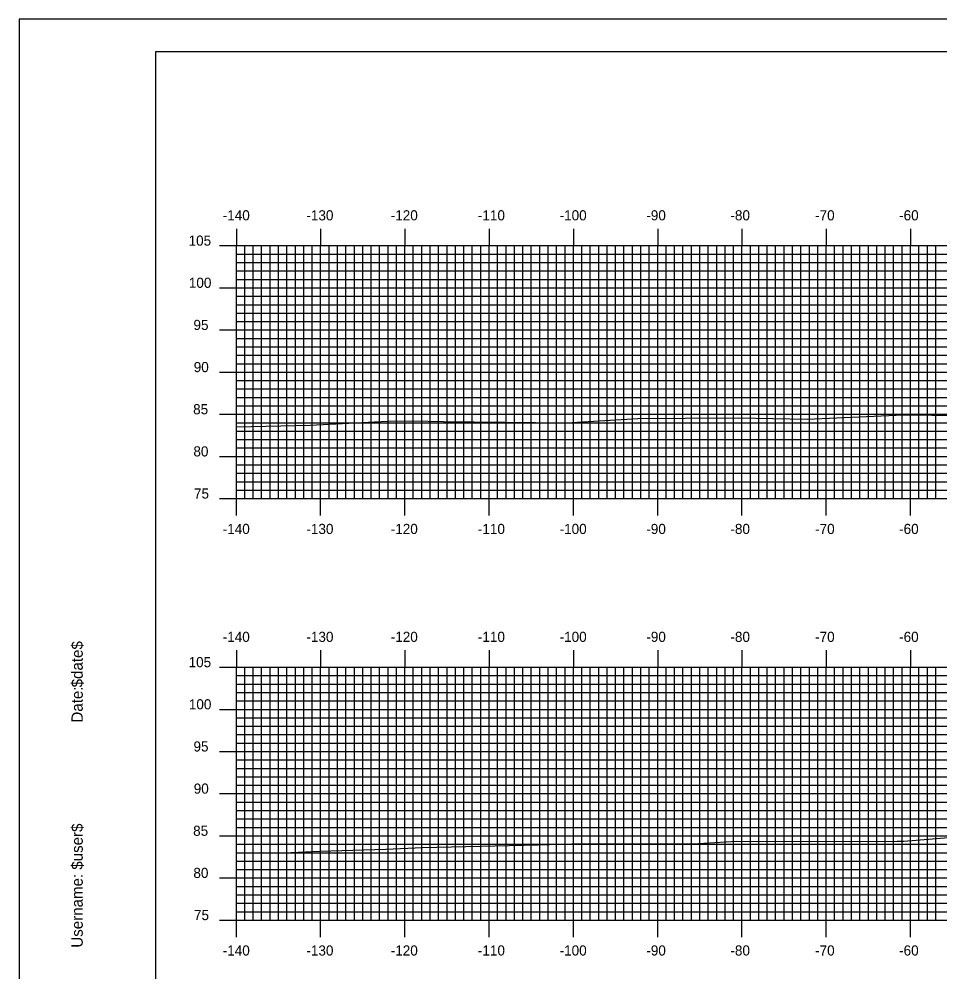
# Model space of a CAD drawing. Extents: x 2059 to 2403, y -1658 to -1438.
# Drawn here: x 2059.4 to 2168.7, y -1550.7 to -1437.7 of the extents above; entities that cross this region are included whole.
import ezdxf

# ---------------------------------------------------------------- set-up
doc = ezdxf.new("R2010")
doc.units = 0
for name, color, linetype in [('BORDER', 7, 'Continuous'), ('H_V ANNOTATION', 7, 'Continuous'), ('MAJOR', 7, 'Continuous'), ('MINOR', 7, 'Continuous'), ('PLOT BOUNDARY', 7, 'Continuous'), ('S_Roadway_Centerline', 7, 'Continuous')]:
    doc.layers.add(name, color=color, linetype=linetype)

msp = doc.modelspace()

# ---------------------------------------------------------------- linework, layer by layer
at = {"layer": 'BORDER'}
msp.add_lwpolyline([(2075.59, -1651.6), (2395.59, -1651.6), (2395.59, -1441.6), (2075.59, -1441.6)], close=True, dxfattribs=at)
at = {"layer": 'MAJOR'}
for p, q in [((2085.19, -1462.6), (2085.19, -1464.6)), ((2095.19, -1462.6), (2095.19, -1464.6)), ((2105.19, -1462.6), (2105.19, -1464.6)), ((2115.19, -1462.6), (2115.19, -1464.6)), ((2125.19, -1462.6), (2125.19, -1464.6)), ((2135.19, -1462.6), (2135.19, -1464.6)), ((2145.19, -1462.6), (2145.19, -1464.6)), ((2155.19, -1462.6), (2155.19, -1464.6)), ((2165.19, -1462.6), (2165.19, -1464.6)), ((2083.18, -1464.6), (2085.19, -1464.6)), ((2085.19, -1464.6), (2365.19, -1464.6)), ((2085.19, -1494.6), (2085.19, -1464.6)), ((2085.19, -1494.6), (2085.19, -1464.6)), ((2085.19, -1464.6), (2365.19, -1464.6)), ((2095.19, -1494.6), (2095.19, -1464.6)), ((2105.19, -1494.6), (2105.19, -1464.6)), ((2115.19, -1494.6), (2115.19, -1464.6)), ((2125.19, -1494.6), (2125.19, -1464.6)), ((2135.19, -1494.6), (2135.19, -1464.6)), ((2145.19, -1494.6), (2145.19, -1464.6)), ((2155.19, -1494.6), (2155.19, -1464.6)), ((2165.19, -1494.6), (2165.19, -1464.6)), ((2083.18, -1469.6), (2085.19, -1469.6)), ((2085.19, -1469.6), (2365.19, -1469.6)), ((2083.18, -1474.6), (2085.19, -1474.6)), ((2085.19, -1474.6), (2365.19, -1474.6)), ((2083.18, -1479.6), (2085.19, -1479.6)), ((2085.19, -1479.6), (2365.19, -1479.6)), ((2083.18, -1484.6), (2085.19, -1484.6)), ((2085.19, -1484.6), (2365.19, -1484.6)), ((2083.18, -1489.6), (2085.19, -1489.6)), ((2085.19, -1489.6), (2365.19, -1489.6)), ((2083.18, -1494.6), (2085.19, -1494.6)), ((2085.19, -1494.6), (2365.19, -1494.6)), ((2085.19, -1494.6), (2365.19, -1494.6)), ((2085.19, -1496.61), (2085.19, -1494.6)), ((2095.19, -1496.61), (2095.19, -1494.6)), ((2105.19, -1496.61), (2105.19, -1494.6)), ((2115.19, -1496.61), (2115.19, -1494.6)), ((2125.19, -1496.61), (2125.19, -1494.6)), ((2135.19, -1496.61), (2135.19, -1494.6)), ((2145.19, -1496.61), (2145.19, -1494.6)), ((2155.19, -1496.61), (2155.19, -1494.6)), ((2165.19, -1496.61), (2165.19, -1494.6)), ((2085.19, -1512.6), (2085.19, -1514.6)), ((2095.19, -1512.6), (2095.19, -1514.6)), ((2105.19, -1512.6), (2105.19, -1514.6)), ((2115.19, -1512.6), (2115.19, -1514.6)), ((2125.19, -1512.6), (2125.19, -1514.6)), ((2135.19, -1512.6), (2135.19, -1514.6)), ((2145.19, -1512.6), (2145.19, -1514.6)), ((2155.19, -1512.6), (2155.19, -1514.6)), ((2165.19, -1512.6), (2165.19, -1514.6)), ((2083.18, -1514.6), (2085.19, -1514.6)), ((2085.19, -1514.6), (2365.19, -1514.6)), ((2085.19, -1544.6), (2085.19, -1514.6)), ((2085.19, -1544.6), (2085.19, -1514.6)), ((2085.19, -1514.6), (2365.19, -1514.6)), ((2095.19, -1544.6), (2095.19, -1514.6)), ((2105.19, -1544.6), (2105.19, -1514.6)), ((2115.19, -1544.6), (2115.19, -1514.6)), ((2125.19, -1544.6), (2125.19, -1514.6)), ((2135.19, -1544.6), (2135.19, -1514.6)), ((2145.19, -1544.6), (2145.19, -1514.6)), ((2155.19, -1544.6), (2155.19, -1514.6)), ((2165.19, -1544.6), (2165.19, -1514.6)), ((2083.18, -1519.6), (2085.19, -1519.6)), ((2085.19, -1519.6), (2365.19, -1519.6)), ((2083.18, -1524.6), (2085.19, -1524.6)), ((2085.19, -1524.6), (2365.19, -1524.6)), ((2083.18, -1529.6), (2085.19, -1529.6)), ((2085.19, -1529.6), (2365.19, -1529.6)), ((2083.18, -1534.6), (2085.19, -1534.6)), ((2085.19, -1534.6), (2365.19, -1534.6)), ((2083.18, -1539.6), (2085.19, -1539.6)), ((2085.19, -1539.6), (2365.19, -1539.6)), ((2083.18, -1544.6), (2085.19, -1544.6)), ((2085.19, -1544.6), (2365.19, -1544.6)), ((2085.19, -1544.6), (2365.19, -1544.6)), ((2085.19, -1546.61), (2085.19, -1544.6)), ((2095.19, -1546.61), (2095.19, -1544.6)), ((2105.19, -1546.61), (2105.19, -1544.6)), ((2115.19, -1546.61), (2115.19, -1544.6)), ((2125.19, -1546.61), (2125.19, -1544.6)), ((2135.19, -1546.61), (2135.19, -1544.6)), ((2145.19, -1546.61), (2145.19, -1544.6)), ((2155.19, -1546.61), (2155.19, -1544.6)), ((2165.19, -1546.61), (2165.19, -1544.6))]:
    msp.add_line(p, q, dxfattribs=at)
at = {"layer": 'MINOR'}
for p, q in [((2086.19, -1494.6), (2086.19, -1464.6)), ((2087.19, -1494.6), (2087.19, -1464.6)), ((2088.19, -1494.6), (2088.19, -1464.6)), ((2089.19, -1494.6), (2089.19, -1464.6)), ((2090.19, -1494.6), (2090.19, -1464.6)), ((2091.19, -1494.6), (2091.19, -1464.6)), ((2092.19, -1494.6), (2092.19, -1464.6)), ((2093.19, -1494.6), (2093.19, -1464.6)), ((2094.19, -1494.6), (2094.19, -1464.6)), ((2096.19, -1494.6), (2096.19, -1464.6)), ((2097.19, -1494.6), (2097.19, -1464.6)), ((2098.19, -1494.6), (2098.19, -1464.6)), ((2099.19, -1494.6), (2099.19, -1464.6)), ((2100.19, -1494.6), (2100.19, -1464.6)), ((2101.19, -1494.6), (2101.19, -1464.6)), ((2102.19, -1494.6), (2102.19, -1464.6)), ((2103.19, -1494.6), (2103.19, -1464.6)), ((2104.19, -1494.6), (2104.19, -1464.6)), ((2106.19, -1494.6), (2106.19, -1464.6)), ((2107.19, -1494.6), (2107.19, -1464.6)), ((2108.19, -1494.6), (2108.19, -1464.6)), ((2109.19, -1494.6), (2109.19, -1464.6)), ((2110.19, -1494.6), (2110.19, -1464.6)), ((2111.19, -1494.6), (2111.19, -1464.6)), ((2112.19, -1494.6), (2112.19, -1464.6)), ((2113.19, -1494.6), (2113.19, -1464.6)), ((2114.19, -1494.6), (2114.19, -1464.6)), ((2116.19, -1494.6), (2116.19, -1464.6)), ((2117.19, -1494.6), (2117.19, -1464.6)), ((2118.19, -1494.6), (2118.19, -1464.6)), ((2119.19, -1494.6), (2119.19, -1464.6)), ((2120.19, -1494.6), (2120.19, -1464.6)), ((2121.19, -1494.6), (2121.19, -1464.6)), ((2122.19, -1494.6), (2122.19, -1464.6)), ((2123.19, -1494.6), (2123.19, -1464.6)), ((2124.19, -1494.6), (2124.19, -1464.6)), ((2126.19, -1494.6), (2126.19, -1464.6)), ((2127.19, -1494.6), (2127.19, -1464.6)), ((2128.19, -1494.6), (2128.19, -1464.6)), ((2129.19, -1494.6), (2129.19, -1464.6)), ((2130.19, -1494.6), (2130.19, -1464.6)), ((2131.19, -1494.6), (2131.19, -1464.6)), ((2132.19, -1494.6), (2132.19, -1464.6)), ((2133.19, -1494.6), (2133.19, -1464.6)), ((2134.19, -1494.6), (2134.19, -1464.6)), ((2136.19, -1494.6), (2136.19, -1464.6)), ((2137.19, -1494.6), (2137.19, -1464.6)), ((2138.19, -1494.6), (2138.19, -1464.6)), ((2139.19, -1494.6), (2139.19, -1464.6)), ((2140.19, -1494.6), (2140.19, -1464.6)), ((2141.19, -1494.6), (2141.19, -1464.6)), ((2142.19, -1494.6), (2142.19, -1464.6)), ((2143.19, -1494.6), (2143.19, -1464.6)), ((2144.19, -1494.6), (2144.19, -1464.6)), ((2146.19, -1494.6), (2146.19, -1464.6)), ((2147.19, -1494.6), (2147.19, -1464.6)), ((2148.19, -1494.6), (2148.19, -1464.6)), ((2149.19, -1494.6), (2149.19, -1464.6)), ((2150.19, -1494.6), (2150.19, -1464.6)), ((2151.19, -1494.6), (2151.19, -1464.6)), ((2152.19, -1494.6), (2152.19, -1464.6)), ((2153.19, -1494.6), (2153.19, -1464.6)), ((2154.19, -1494.6), (2154.19, -1464.6)), ((2156.19, -1494.6), (2156.19, -1464.6)), ((2157.19, -1494.6), (2157.19, -1464.6)), ((2158.19, -1494.6), (2158.19, -1464.6)), ((2159.19, -1494.6), (2159.19, -1464.6)), ((2160.19, -1494.6), (2160.19, -1464.6)), ((2161.19, -1494.6), (2161.19, -1464.6)), ((2162.19, -1494.6), (2162.19, -1464.6)), ((2163.19, -1494.6), (2163.19, -1464.6)), ((2164.19, -1494.6), (2164.19, -1464.6)), ((2166.19, -1494.6), (2166.19, -1464.6)), ((2167.19, -1494.6), (2167.19, -1464.6)), ((2168.19, -1494.6), (2168.19, -1464.6)), ((2085.19, -1465.6), (2365.19, -1465.6)), ((2085.19, -1465.6), (2087.19, -1465.6)), ((2085.19, -1466.6), (2365.19, -1466.6)), ((2085.19, -1466.6), (2087.19, -1466.6)), ((2085.19, -1467.6), (2365.19, -1467.6)), ((2085.19, -1467.6), (2087.19, -1467.6)), ((2085.19, -1468.6), (2365.19, -1468.6)), ((2085.19, -1468.6), (2087.19, -1468.6)), ((2085.19, -1470.6), (2365.19, -1470.6)), ((2085.19, -1470.6), (2087.19, -1470.6)), ((2085.19, -1471.6), (2365.19, -1471.6)), ((2085.19, -1471.6), (2087.19, -1471.6)), ((2085.19, -1472.6), (2365.19, -1472.6)), ((2085.19, -1472.6), (2087.19, -1472.6)), ((2085.19, -1473.6), (2365.19, -1473.6)), ((2085.19, -1473.6), (2087.19, -1473.6)), ((2085.19, -1475.6), (2365.19, -1475.6)), ((2085.19, -1475.6), (2087.19, -1475.6)), ((2085.19, -1476.6), (2365.19, -1476.6)), ((2085.19, -1476.6), (2087.19, -1476.6)), ((2085.19, -1477.6), (2365.19, -1477.6)), ((2085.19, -1477.6), (2087.19, -1477.6)), ((2085.19, -1478.6), (2365.19, -1478.6)), ((2085.19, -1478.6), (2087.19, -1478.6)), ((2085.19, -1480.6), (2365.19, -1480.6)), ((2085.19, -1480.6), (2087.19, -1480.6)), ((2085.19, -1481.6), (2365.19, -1481.6)), ((2085.19, -1481.6), (2087.19, -1481.6)), ((2085.19, -1482.6), (2365.19, -1482.6)), ((2085.19, -1482.6), (2087.19, -1482.6)), ((2085.19, -1483.6), (2365.19, -1483.6)), ((2085.19, -1483.6), (2087.19, -1483.6)), ((2085.19, -1485.6), (2365.19, -1485.6)), ((2085.19, -1485.6), (2087.19, -1485.6)), ((2085.19, -1486.6), (2365.19, -1486.6)), ((2085.19, -1486.6), (2087.19, -1486.6)), ((2085.19, -1487.6), (2365.19, -1487.6)), ((2085.19, -1487.6), (2087.19, -1487.6)), ((2085.19, -1488.6), (2365.19, -1488.6)), ((2085.19, -1488.6), (2087.19, -1488.6)), ((2085.19, -1490.6), (2365.19, -1490.6)), ((2085.19, -1490.6), (2087.19, -1490.6)), ((2085.19, -1491.6), (2365.19, -1491.6)), ((2085.19, -1491.6), (2087.19, -1491.6)), ((2085.19, -1492.6), (2365.19, -1492.6)), ((2085.19, -1492.6), (2087.19, -1492.6)), ((2085.19, -1493.6), (2365.19, -1493.6)), ((2085.19, -1493.6), (2087.19, -1493.6)), ((2085.19, -1515.6), (2365.19, -1515.6)), ((2085.19, -1515.6), (2087.19, -1515.6)), ((2086.19, -1544.6), (2086.19, -1514.6)), ((2087.19, -1544.6), (2087.19, -1514.6)), ((2088.19, -1544.6), (2088.19, -1514.6)), ((2089.19, -1544.6), (2089.19, -1514.6)), ((2090.19, -1544.6), (2090.19, -1514.6)), ((2091.19, -1544.6), (2091.19, -1514.6)), ((2092.19, -1544.6), (2092.19, -1514.6)), ((2093.19, -1544.6), (2093.19, -1514.6)), ((2094.19, -1544.6), (2094.19, -1514.6)), ((2096.19, -1544.6), (2096.19, -1514.6)), ((2097.19, -1544.6), (2097.19, -1514.6)), ((2098.19, -1544.6), (2098.19, -1514.6)), ((2099.19, -1544.6), (2099.19, -1514.6)), ((2100.19, -1544.6), (2100.19, -1514.6)), ((2101.19, -1544.6), (2101.19, -1514.6)), ((2102.19, -1544.6), (2102.19, -1514.6)), ((2103.19, -1544.6), (2103.19, -1514.6)), ((2104.19, -1544.6), (2104.19, -1514.6)), ((2106.19, -1544.6), (2106.19, -1514.6)), ((2107.19, -1544.6), (2107.19, -1514.6)), ((2108.19, -1544.6), (2108.19, -1514.6)), ((2109.19, -1544.6), (2109.19, -1514.6)), ((2110.19, -1544.6), (2110.19, -1514.6)), ((2111.19, -1544.6), (2111.19, -1514.6)), ((2112.19, -1544.6), (2112.19, -1514.6)), ((2113.19, -1544.6), (2113.19, -1514.6)), ((2114.19, -1544.6), (2114.19, -1514.6)), ((2116.19, -1544.6), (2116.19, -1514.6)), ((2117.19, -1544.6), (2117.19, -1514.6)), ((2118.19, -1544.6), (2118.19, -1514.6)), ((2119.19, -1544.6), (2119.19, -1514.6)), ((2120.19, -1544.6), (2120.19, -1514.6)), ((2121.19, -1544.6), (2121.19, -1514.6)), ((2122.19, -1544.6), (2122.19, -1514.6)), ((2123.19, -1544.6), (2123.19, -1514.6)), ((2124.19, -1544.6), (2124.19, -1514.6)), ((2126.19, -1544.6), (2126.19, -1514.6)), ((2127.19, -1544.6), (2127.19, -1514.6)), ((2128.19, -1544.6), (2128.19, -1514.6)), ((2129.19, -1544.6), (2129.19, -1514.6)), ((2130.19, -1544.6), (2130.19, -1514.6)), ((2131.19, -1544.6), (2131.19, -1514.6)), ((2132.19, -1544.6), (2132.19, -1514.6)), ((2133.19, -1544.6), (2133.19, -1514.6)), ((2134.19, -1544.6), (2134.19, -1514.6)), ((2136.19, -1544.6), (2136.19, -1514.6)), ((2137.19, -1544.6), (2137.19, -1514.6)), ((2138.19, -1544.6), (2138.19, -1514.6)), ((2139.19, -1544.6), (2139.19, -1514.6)), ((2140.19, -1544.6), (2140.19, -1514.6)), ((2141.19, -1544.6), (2141.19, -1514.6)), ((2142.19, -1544.6), (2142.19, -1514.6)), ((2143.19, -1544.6), (2143.19, -1514.6)), ((2144.19, -1544.6), (2144.19, -1514.6)), ((2146.19, -1544.6), (2146.19, -1514.6)), ((2147.19, -1544.6), (2147.19, -1514.6)), ((2148.19, -1544.6), (2148.19, -1514.6)), ((2149.19, -1544.6), (2149.19, -1514.6)), ((2150.19, -1544.6), (2150.19, -1514.6)), ((2151.19, -1544.6), (2151.19, -1514.6)), ((2152.19, -1544.6), (2152.19, -1514.6)), ((2153.19, -1544.6), (2153.19, -1514.6)), ((2154.19, -1544.6), (2154.19, -1514.6)), ((2156.19, -1544.6), (2156.19, -1514.6)), ((2157.19, -1544.6), (2157.19, -1514.6)), ((2158.19, -1544.6), (2158.19, -1514.6)), ((2159.19, -1544.6), (2159.19, -1514.6)), ((2160.19, -1544.6), (2160.19, -1514.6)), ((2161.19, -1544.6), (2161.19, -1514.6)), ((2162.19, -1544.6), (2162.19, -1514.6)), ((2163.19, -1544.6), (2163.19, -1514.6)), ((2164.19, -1544.6), (2164.19, -1514.6)), ((2166.19, -1544.6), (2166.19, -1514.6)), ((2167.19, -1544.6), (2167.19, -1514.6)), ((2168.19, -1544.6), (2168.19, -1514.6)), ((2085.19, -1516.6), (2365.19, -1516.6)), ((2085.19, -1516.6), (2087.19, -1516.6)), ((2085.19, -1517.6), (2365.19, -1517.6)), ((2085.19, -1517.6), (2087.19, -1517.6)), ((2085.19, -1518.6), (2365.19, -1518.6)), ((2085.19, -1518.6), (2087.19, -1518.6)), ((2085.19, -1520.6), (2365.19, -1520.6)), ((2085.19, -1520.6), (2087.19, -1520.6)), ((2085.19, -1521.6), (2365.19, -1521.6)), ((2085.19, -1521.6), (2087.19, -1521.6)), ((2085.19, -1522.6), (2365.19, -1522.6)), ((2085.19, -1522.6), (2087.19, -1522.6)), ((2085.19, -1523.6), (2365.19, -1523.6)), ((2085.19, -1523.6), (2087.19, -1523.6)), ((2085.19, -1525.6), (2365.19, -1525.6)), ((2085.19, -1525.6), (2087.19, -1525.6)), ((2085.19, -1526.6), (2365.19, -1526.6)), ((2085.19, -1526.6), (2087.19, -1526.6)), ((2085.19, -1527.6), (2365.19, -1527.6)), ((2085.19, -1527.6), (2087.19, -1527.6)), ((2085.19, -1528.6), (2365.19, -1528.6)), ((2085.19, -1528.6), (2087.19, -1528.6)), ((2085.19, -1530.6), (2365.19, -1530.6)), ((2085.19, -1530.6), (2087.19, -1530.6)), ((2085.19, -1531.6), (2365.19, -1531.6)), ((2085.19, -1531.6), (2087.19, -1531.6)), ((2085.19, -1532.6), (2365.19, -1532.6)), ((2085.19, -1532.6), (2087.19, -1532.6)), ((2085.19, -1533.6), (2365.19, -1533.6)), ((2085.19, -1533.6), (2087.19, -1533.6)), ((2085.19, -1535.6), (2365.19, -1535.6)), ((2085.19, -1535.6), (2087.19, -1535.6)), ((2085.19, -1536.6), (2365.19, -1536.6)), ((2085.19, -1536.6), (2087.19, -1536.6)), ((2085.19, -1537.6), (2365.19, -1537.6)), ((2085.19, -1537.6), (2087.19, -1537.6)), ((2085.19, -1538.6), (2365.19, -1538.6)), ((2085.19, -1538.6), (2087.19, -1538.6)), ((2085.19, -1540.6), (2365.19, -1540.6)), ((2085.19, -1540.6), (2087.19, -1540.6)), ((2085.19, -1541.6), (2365.19, -1541.6)), ((2085.19, -1541.6), (2087.19, -1541.6)), ((2085.19, -1542.6), (2365.19, -1542.6)), ((2085.19, -1542.6), (2087.19, -1542.6)), ((2085.19, -1543.6), (2365.19, -1543.6)), ((2085.19, -1543.6), (2087.19, -1543.6))]:
    msp.add_line(p, q, dxfattribs=at)
at = {"layer": 'PLOT BOUNDARY'}
msp.add_lwpolyline([(2059.4, -1657.72), (2399.4, -1657.72), (2399.4, -1437.72), (2059.4, -1437.72)], close=True, dxfattribs=at)
at = {"layer": 'S_Roadway_Centerline'}
for points in [[(2085.19, -1486.1), (2093.95, -1485.89), (2103.12, -1485.42), (2106.11, -1485.37), (2109.79, -1485.44), (2124.31, -1485.62), (2132.82, -1485.11), (2138.45, -1485.05), (2144.78, -1485.04), (2152.92, -1485.2), (2163.49, -1484.7), (2165, -1484.67), (2167.74, -1484.69), (2185.15, -1484.97)], [(2085.19, -1536.63), (2088.36, -1536.56), (2090.81, -1536.61), (2095.11, -1536.44), (2102.94, -1536.19), (2107.29, -1535.99), (2121.02, -1535.66), (2125, -1535.55), (2128.66, -1535.57), (2139.35, -1535.57), (2144.59, -1535.24), (2161.13, -1535.29), (2163.6, -1535.22), (2164.4, -1535.24), (2165.87, -1535.12), (2175.52, -1534.33)]]:
    msp.add_lwpolyline(points, dxfattribs=at)

# ---------------------------------------------------------------- texts
at = {"layer": 'BORDER'}
for s, p in [('$date$', (2066.96, -1516.99)), ('Date:', (2066.96, -1521.17)), ('$user$', (2066.96, -1538.62)), ('Username:', (2066.96, -1547.87))]:
    msp.add_text(s, height=1.339, rotation=90, dxfattribs=at).set_placement(p)
at = {"layer": 'H_V ANNOTATION'}
for s, p in [('-140', (2083.57, -1461.6)), ('-130', (2093.5, -1461.6)), ('-120', (2103.51, -1461.6)), ('-110', (2113.85, -1461.6)), ('-100', (2123.55, -1461.6)), ('-90', (2133.84, -1461.6)), ('-80', (2143.82, -1461.6)), ('-70', (2153.87, -1461.6)), ('-60', (2163.84, -1461.6)), ('105', (2079.52, -1464.6)), ('100', (2079.55, -1469.6)), ('95', (2080.1, -1474.6)), ('90', (2080.13, -1479.6)), ('85', (2080.06, -1484.6)), ('80', (2080.09, -1489.6)), ('75', (2080.16, -1494.6)), ('-140', (2083.57, -1498.8)), ('-130', (2093.5, -1498.8)), ('-120', (2103.51, -1498.8)), ('-110', (2113.85, -1498.8)), ('-100', (2123.55, -1498.8)), ('-90', (2133.84, -1498.8)), ('-80', (2143.82, -1498.8)), ('-70', (2153.87, -1498.8)), ('-60', (2163.84, -1498.8)), ('-140', (2083.57, -1511.6)), ('-130', (2093.5, -1511.6)), ('-120', (2103.51, -1511.6)), ('-110', (2113.85, -1511.6)), ('-100', (2123.55, -1511.6)), ('-90', (2133.84, -1511.6)), ('-80', (2143.82, -1511.6)), ('-70', (2153.87, -1511.6)), ('-60', (2163.84, -1511.6)), ('105', (2079.52, -1514.6)), ('100', (2079.55, -1519.6)), ('95', (2080.1, -1524.6)), ('90', (2080.13, -1529.6)), ('85', (2080.06, -1534.6)), ('80', (2080.09, -1539.6)), ('75', (2080.16, -1544.6)), ('-140', (2083.57, -1548.8)), ('-130', (2093.5, -1548.8)), ('-120', (2103.51, -1548.8)), ('-110', (2113.85, -1548.8)), ('-100', (2123.55, -1548.8)), ('-90', (2133.84, -1548.8)), ('-80', (2143.82, -1548.8)), ('-70', (2153.87, -1548.8)), ('-60', (2163.84, -1548.8))]:
    msp.add_text(s, height=1.2, dxfattribs=at).set_placement(p)
at = {"layer": 'MAJOR'}
for p in [(2085.18, -1494.6), (2085.18, -1544.6)]:
    msp.add_text('-', height=0.012, dxfattribs=at).set_placement(p)

doc.saveas('drawing.dxf')
